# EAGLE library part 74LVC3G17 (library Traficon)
SN74LVC3G17 TRIPLE SCHMITT-TRIGGER BUFFER CT: 2 oct. 2008 TI-DC8-package = NXP SOT765-1 package
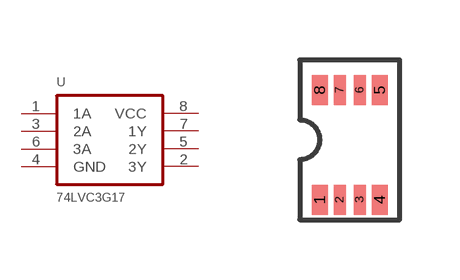
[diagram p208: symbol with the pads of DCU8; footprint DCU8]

Designator prefix U

## 74LVC3G17  [DCU8]
1  1A
2  3Y
3  2A
4  GND
5  2Y
6  3A
7  1Y
8  VCC

## Footprint DCU8 (pad centres in mm)
smd 0.4 x 0.75: 1 -1,-1.5; 4 0.5,-1.5; 5 0.5,1.25; 8 -1,1.25
smd 0.3 x 0.75: 2 -0.5,-1.5; 3 0,-1.5; 6 0,1.25; 7 -0.5,1.25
